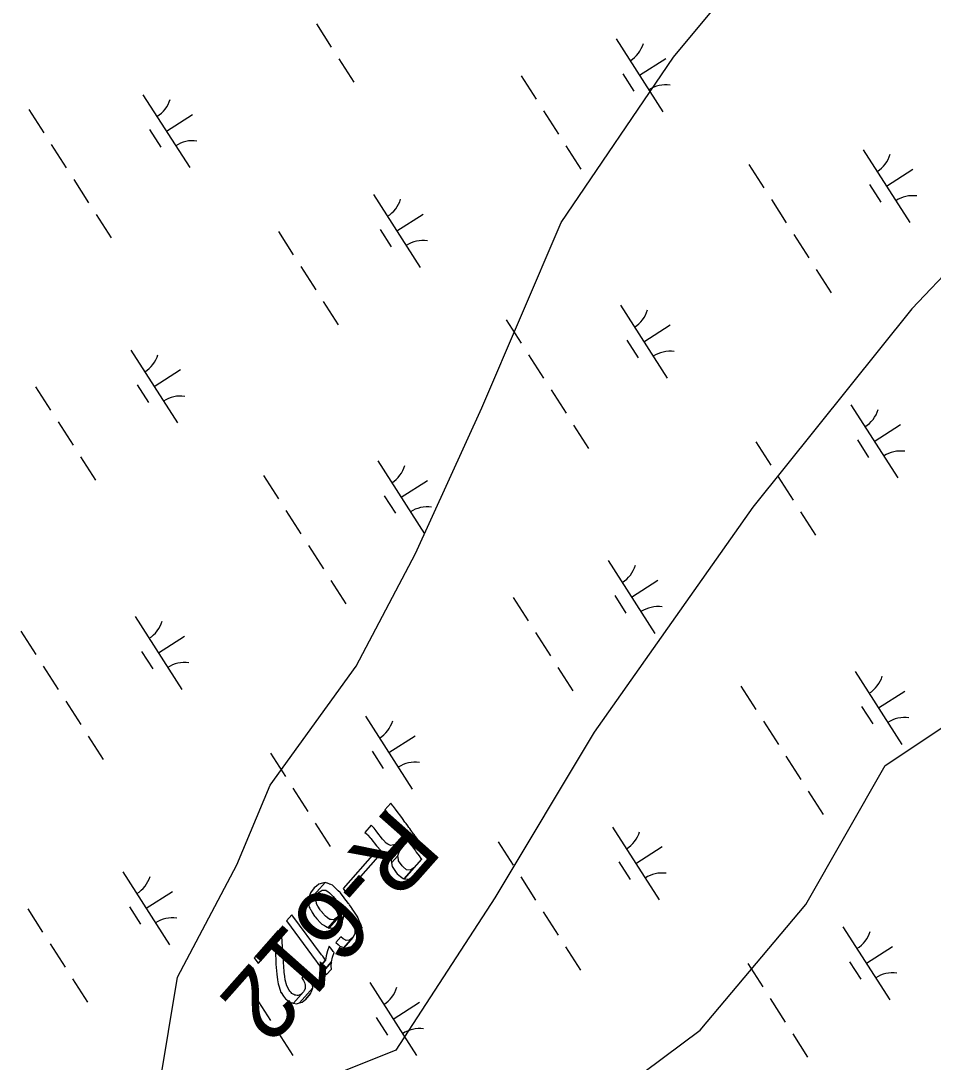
# Model space of a CAD drawing. Extents: x 3962991 to 3983549, y 181631 to 204078.
# Drawn here: x 3978966 to 3979493, y 189800 to 190401 of the extents above; entities that cross this region are included whole.
import ezdxf

# ---------------------------------------------------------------- set-up
doc = ezdxf.new("R2010")
doc.units = 0
for name, color, linetype in [('V-ANNO-MASK', 7, 'Continuous'), ('V-ANNO-MASK2', 7, 'Continuous'), ('V-RIVR-RANG-IDEN', 7, 'Continuous'), ('V-SITE-VEGE', 7, 'Continuous'), ('V-WETL-SWMP', 7, 'Continuous')]:
    doc.layers.add(name, color=color, linetype=linetype)

msp = doc.modelspace()

# ---------------------------------------------------------------- linework, layer by layer
at = {"layer": 'V-ANNO-MASK2'}
for points in [[(3979181.04, 189948.26), (3979179.85, 189949.87), (3979176.44, 189946.02), (3979177.63, 189944.41), (3979177.88, 189944.07), (3979179.1, 189942.43), (3979179.46, 189941.93), (3979182.68, 189937.59), (3979183.08, 189937.04), (3979184.58, 189935.01), (3979185.2, 189934.18), (3979186.18, 189932.84), (3979186.89, 189931.88), (3979187.12, 189931.58), (3979187.31, 189931.32), (3979177.97, 189920.78), (3979179.61, 189920.89), (3979182.21, 189922.34), (3979181.06, 189920.51), (3979179.97, 189917.41), (3979180.03, 189917.04), (3979189.75, 189928.01), (3979189.87, 189927.86), (3979190.5, 189927), (3979191.55, 189925.59), (3979191.89, 189925.13), (3979193.98, 189922.3), (3979194.53, 189921.56), (3979196.09, 189919.45), (3979197.23, 189917.91), (3979197.47, 189917.59), (3979197.47, 189917.59), (3979197.57, 189917.46), (3979197.61, 189917.39), (3979187.58, 189906.06), (3979191.21, 189905.86), (3979194.53, 189907.72), (3979197.6, 189910.93), (3979203.62, 189917.72), (3979203.51, 189917.86), (3979202.76, 189918.89), (3979201.02, 189921.24), (3979200.97, 189921.3), (3979200.87, 189921.43), (3979200.64, 189921.75), (3979199.5, 189923.3), (3979197.94, 189925.4), (3979197.39, 189926.15), (3979195.29, 189928.98), (3979194.96, 189929.43), (3979193.91, 189930.85), (3979193.28, 189931.71), (3979193.16, 189931.86), (3979192.99, 189932.1), (3979192.23, 189933.13), (3979192.02, 189933.42), (3979191.42, 189934.22), (3979190.72, 189935.17), (3979190.53, 189935.43), (3979190.3, 189935.73), (3979189.59, 189936.7), (3979188.61, 189938.02), (3979187.99, 189938.86), (3979186.49, 189940.89), (3979186.09, 189941.44), (3979182.87, 189945.78), (3979182.51, 189946.28), (3979181.29, 189947.91)], [(3979169.9, 189935.68), (3979168.53, 189937.1), (3979164.81, 189932.9), (3979166.32, 189931.63), (3979166.61, 189931.34), (3979167.98, 189929.87), (3979168.36, 189929.39), (3979171.63, 189925.12), (3979172.05, 189924.58), (3979173.76, 189922.79), (3979174.46, 189922.05), (3979175.94, 189921.28), (3979177.01, 189920.72), (3979177.53, 189920.76), (3979177.97, 189920.78), (3979184.09, 189927.69), (3979182.08, 189925.89), (3979181.49, 189925.78), (3979179.6, 189925.41), (3979178.1, 189926.17), (3979177.16, 189926.63), (3979175.51, 189928.49), (3979175.06, 189928.98), (3979171.84, 189933.32), (3979171.46, 189933.8), (3979170.19, 189935.38)], [(3979172.59, 189918.75), (3979170.68, 189921.33), (3979152.24, 189900.51), (3979154.15, 189897.92)], [(3979184.83, 189922.17), (3979186.96, 189924.86), (3979180.03, 189917.04), (3979180.07, 189916.79), (3979180.27, 189915.45), (3979183.8, 189919.43)], [(3979184.21, 189917.3), (3979183.8, 189919.43), (3979180.27, 189915.45), (3979180.61, 189913.23), (3979180.93, 189912.76), (3979182.94, 189909.83), (3979183.46, 189909.06), (3979185.49, 189907.48), (3979186.98, 189906.33), (3979187.28, 189906.08), (3979187.49, 189906.07), (3979193.11, 189912.42), (3979192.56, 189912.04), (3979191.25, 189911.15), (3979188.93, 189911.36), (3979186.99, 189913.04), (3979186.3, 189913.63), (3979184.34, 189916.61)], [(3979194.86, 189914.28), (3979193.1, 189912.41), (3979187.49, 189906.07), (3979187.58, 189906.06)], [(3979136.93, 189902), (3979135.66, 189900.9), (3979133.4, 189898.01), (3979133.2, 189897.44), (3979133.21, 189897.45), (3979132.09, 189894.25), (3979132.24, 189893.19), (3979141.91, 189904.11), (3979140.47, 189903.72), (3979138.21, 189903.1)], [(3979143.14, 189903.66), (3979141.9, 189904.1), (3979132.24, 189893.19), (3979132.46, 189891.6), (3979138.56, 189898.48), (3979139.03, 189898.77), (3979140.31, 189899.55), (3979141.08, 189899.55), (3979141.33, 189899.55), (3979142.31, 189899.54), (3979143.01, 189899.07), (3979143.4, 189898.81), (3979144.53, 189898.03), (3979146.16, 189896.26), (3979146.5, 189895.89), (3979147.51, 189894.79), (3979147.63, 189894.61), (3979149.1, 189892.35), (3979149.77, 189891.31), (3979149.83, 189891.07), (3979149.84, 189891.08), (3979150.37, 189889.13), (3979150.57, 189888.38), (3979150.29, 189886.28), (3979150.26, 189886.03), (3979148.95, 189883.87), (3979143.7, 189877.94), (3979144.08, 189877.73), (3979144.21, 189877.74), (3979152.89, 189887.54), (3979152.91, 189887.51), (3979153.77, 189886.3), (3979154.34, 189885.5), (3979154.49, 189885.28), (3979155.34, 189884.07), (3979157.63, 189880.55), (3979157.68, 189880.45), (3979157.77, 189880.25), (3979158.55, 189878.46), (3979159.1, 189877.22), (3979159.11, 189877.02), (3979159.12, 189876.24), (3979159.16, 189874.54), (3979158.85, 189873.98), (3979157.88, 189872.23), (3979152.72, 189866.42), (3979152.85, 189866.37), (3979152.85, 189866.37), (3979153.57, 189866.1), (3979157.12, 189867.02), (3979162.71, 189873.33), (3979163.09, 189876.85), (3979163.22, 189878.08), (3979163.17, 189878.21), (3979162.99, 189878.65), (3979162.93, 189878.8), (3979162.44, 189879.99), (3979162.22, 189880.53), (3979162.16, 189880.67), (3979161.63, 189881.94), (3979160.88, 189883.76), (3979160.79, 189883.97), (3979160.74, 189884.06), (3979158.41, 189887.53), (3979157.58, 189888.76), (3979157.43, 189888.99), (3979156.88, 189889.81), (3979156.04, 189891.05), (3979156.02, 189891.08), (3979155.96, 189891.15), (3979155.7, 189891.5), (3979155.42, 189891.86), (3979155.34, 189891.98), (3979154.61, 189892.94), (3979154.21, 189893.47), (3979153.16, 189894.83), (3979153.04, 189895), (3979152.3, 189895.97), (3979150.7, 189898.08), (3979150.55, 189898.22), (3979149.49, 189899.26), (3979149.13, 189899.61), (3979147.42, 189901.28), (3979146.44, 189902.24), (3979146.1, 189902.57), (3979145.27, 189902.88), (3979144.52, 189903.15), (3979144.33, 189903.22), (3979143.74, 189903.43), (3979143.3, 189903.59)], [(3979137.21, 189896.72), (3979138.56, 189898.48), (3979132.46, 189891.6), (3979132.49, 189891.38)], [(3979136.9, 189895.71), (3979137.21, 189896.72), (3979132.49, 189891.38), (3979132.57, 189890.81), (3979132.67, 189890.05), (3979132.7, 189889.81), (3979133.1, 189889.14), (3979133.55, 189888.39), (3979133.8, 189887.97), (3979134.54, 189886.74), (3979135.82, 189884.58), (3979136.16, 189884.2), (3979137.16, 189883.09), (3979137.16, 189883.1), (3979137.29, 189882.94), (3979139.05, 189881), (3979139.85, 189880.1), (3979139.98, 189879.95), (3979141.51, 189879.13), (3979142.1, 189878.81), (3979143.17, 189878.23), (3979143.29, 189878.16), (3979143.7, 189877.94), (3979148.95, 189883.87), (3979147.4, 189882.81), (3979146.93, 189882.48), (3979145.46, 189882.61), (3979144.65, 189882.67), (3979143.28, 189883.68), (3979143.13, 189883.8), (3979142.16, 189884.51), (3979140.45, 189886.51), (3979140.32, 189886.67), (3979139.35, 189887.8), (3979139.08, 189888.26), (3979137.78, 189890.4), (3979137.04, 189891.63), (3979136.93, 189892.21), (3979136.72, 189893.22), (3979136.54, 189894.14), (3979136.49, 189894.37)], [(3979139.89, 189862.31), (3979122.79, 189885.44), (3979119.58, 189881.82), (3979136.69, 189858.7), (3979137.33, 189857.83), (3979138.15, 189856.73), (3979139.02, 189855.55), (3979142.22, 189859.16), (3979141.35, 189860.34), (3979140.53, 189861.44)], [(3979152.89, 189887.49), (3979152.89, 189887.54), (3979144.21, 189877.74), (3979144.26, 189877.75), (3979146.36, 189877.93), (3979147.73, 189878.04), (3979148.82, 189878.86), (3979150.46, 189880.11), (3979152.28, 189882.77), (3979152.42, 189883.33), (3979152.93, 189885.35)], [(3979116.92, 189873.39), (3979114.79, 189876.29), (3979100.92, 189860.62), (3979103.06, 189857.73), (3979103.31, 189857.38), (3979113.12, 189868.45), (3979113.32, 189862.42), (3979113.45, 189859.39), (3979113.55, 189856.91), (3979113.83, 189853.06), (3979113.98, 189851.09), (3979114.46, 189847.86), (3979114.81, 189845.47), (3979115.38, 189843.78), (3979116.46, 189840.58), (3979116.47, 189840.54), (3979117.98, 189838.39), (3979118.47, 189837.69), (3979119.04, 189836.86), (3979119.63, 189836.46), (3979119.98, 189836.2), (3979120.66, 189835.73), (3979121.23, 189835.32), (3979121.62, 189835.04), (3979122.06, 189834.73), (3979122.59, 189834.63), (3979123.09, 189834.53), (3979123.49, 189834.45), (3979123.61, 189834.43), (3979123.68, 189834.41), (3979129.53, 189841.02), (3979128.97, 189840.48), (3979128.06, 189839.61), (3979127.29, 189839.27), (3979126.33, 189838.84), (3979125.75, 189838.9), (3979125.09, 189838.96), (3979124.49, 189839.01), (3979123.87, 189839.35), (3979123.14, 189839.76), (3979122.75, 189839.98), (3979122.28, 189840.52), (3979121.63, 189841.26), (3979121.08, 189841.89), (3979119.87, 189844.38), (3979119.85, 189844.41), (3979118.96, 189847.82), (3979118.68, 189849.84), (3979118.33, 189852.24), (3979118.05, 189855.7), (3979117.89, 189857.64), (3979117.63, 189861.51), (3979117.46, 189863.93), (3979117.3, 189866.91), (3979116.96, 189872.78)], [(3979152.36, 189871.47), (3979151.07, 189872.69), (3979148.14, 189869.37), (3979149.44, 189868.17), (3979150.35, 189867.34), (3979150.45, 189867.24), (3979150.98, 189867.05), (3979152.15, 189866.62), (3979152.29, 189866.57), (3979152.72, 189866.42), (3979157.88, 189872.24), (3979156.06, 189870.83), (3979155.86, 189870.81), (3979154.09, 189870.55), (3979153.61, 189870.81), (3979153.48, 189870.88)], [(3979162.46, 189872.95), (3979162.71, 189873.33), (3979157.12, 189867.02), (3979157.23, 189867.05), (3979160.25, 189869.64), (3979160.26, 189869.65)], [(3979144.93, 189866.42), (3979144.29, 189867.28), (3979143.26, 189864.53), (3979142.49, 189861.63), (3979142.22, 189859.16), (3979139.02, 189855.55), (3979139.46, 189854.96), (3979140.14, 189854.04), (3979140.99, 189852.88), (3979145.68, 189858.18), (3979146.25, 189860.94), (3979147.06, 189863.54), (3979146.62, 189864.13), (3979145.75, 189865.31)], [(3979145.45, 189855.69), (3979145.68, 189858.18), (3979140.99, 189852.88), (3979141.89, 189851.67), (3979142.6, 189850.71), (3979145.58, 189854.08)], [(3979132.25, 189851.77), (3979131.68, 189852.61), (3979128.45, 189848.96), (3979129.02, 189848.13), (3979129.43, 189847.53), (3979129.69, 189847.16), (3979130.03, 189846.3), (3979130.31, 189845.58), (3979130.5, 189845.08), (3979130.5, 189844.26), (3979130.5, 189843.56), (3979130.5, 189842.89), (3979129.84, 189841.61), (3979129.65, 189841.25), (3979129.53, 189841.02), (3979123.68, 189834.41), (3979125.31, 189834.09), (3979127.19, 189834.61), (3979134.77, 189843.17), (3979134.72, 189844.72), (3979134.65, 189846.81), (3979134.65, 189846.9), (3979134.61, 189847), (3979134.46, 189847.37), (3979134.29, 189847.83), (3979134.09, 189848.31), (3979133.87, 189848.88), (3979133.67, 189849.38), (3979133.39, 189850.1), (3979132.92, 189850.8), (3979132.66, 189851.18)], [(3979133.98, 189841.04), (3979134.77, 189843.16), (3979127.19, 189834.61), (3979128.64, 189835), (3979130.54, 189836.53), (3979133.58, 189839.96)], [(3979131.41, 189837.22), (3979133.57, 189839.95), (3979130.54, 189836.53), (3979131.41, 189837.22)]]:
    msp.add_lwpolyline(points, close=True, dxfattribs=at)
at = {"layer": 'V-SITE-VEGE'}
for p, q in [((3979342.99, 190380.22), (3979434.6, 190490.98)), ((3979278.1, 190284.74), (3979342.99, 190380.22)), ((3979556.75, 190315.3), (3979480.41, 190235.1)), ((3979232.3, 190177.81), (3979278.1, 190284.74)), ((3979480.41, 190235.1), (3979388.8, 190120.52)), ((3979194.13, 190093.78), (3979232.3, 190177.81)), ((3979388.8, 190120.52), (3979297.19, 189990.67)), ((3979159.77, 190028.86), (3979194.13, 190093.78)), ((3979465.14, 189971.57), (3979591.1, 190055.59)), ((3979110.15, 189960.11), (3979159.77, 190028.86)), ((3979297.19, 189990.67), (3979239.93, 189895.18)), ((3979419.33, 189891.36), (3979465.14, 189971.57)), ((3979091.07, 189914.28), (3979110.15, 189960.11)), ((3979056.71, 189849.36), (3979091.07, 189914.28)), ((3979239.93, 189895.18), (3979182.68, 189807.34)), ((3979358.27, 189818.8), (3979419.33, 189891.36)), ((3979045.26, 189780.61), (3979056.71, 189849.36)), ((3979209.4, 189708.04), (3979358.27, 189818.8)), ((3979182.68, 189807.34), (3979087.25, 189769.15))]:
    msp.add_line(p, q, dxfattribs=at)
at = {"layer": 'V-WETL-SWMP'}
for p, q in [((3979136.87, 190399.46), (3979145.5, 190385.99)), ((3979309.87, 190390.8), (3979336.85, 190348.71)), ((3979149.82, 190379.26), (3979158.46, 190365.79)), ((3979323.36, 190369.76), (3979338.51, 190379.47)), ((3979313.63, 190370.64), (3979320.1, 190360.54)), ((3979254.96, 190369.51), (3979263.6, 190356.04)), ((3979036.81, 190358.57), (3979063.8, 190316.48)), ((3978970.93, 190350.1), (3978979.57, 190336.63)), ((3979050.3, 190337.53), (3979065.46, 190347.24)), ((3979267.91, 190349.3), (3979276.55, 190335.83)), ((3979040.57, 190338.41), (3979047.05, 190328.31)), ((3978983.88, 190329.89), (3978992.52, 190316.42)), ((3979280.87, 190329.1), (3979289.5, 190315.63)), ((3979452.32, 190326.85), (3979479.3, 190284.76)), ((3979386.44, 190318.38), (3979395.07, 190304.91)), ((3979465.81, 190305.81), (3979480.96, 190315.52)), ((3978996.84, 190309.69), (3979005.47, 190296.22)), ((3979456.08, 190306.69), (3979462.55, 190296.59)), ((3979169.84, 190301.03), (3979196.82, 190258.94)), ((3979399.39, 190298.17), (3979408.02, 190284.7)), ((3979009.79, 190289.48), (3979018.42, 190276.01)), ((3979183.33, 190279.98), (3979198.48, 190289.7)), ((3979173.59, 190280.87), (3979180.07, 190270.77)), ((3979114.93, 190279.73), (3979123.57, 190266.26)), ((3979412.34, 190277.97), (3979420.98, 190264.5)), ((3979127.88, 190259.53), (3979136.52, 190246.06)), ((3979425.29, 190257.76), (3979433.93, 190244.3)), ((3979140.84, 190239.32), (3979149.47, 190225.85)), ((3979312.28, 190237.08), (3979339.27, 190194.99)), ((3979246.4, 190228.6), (3979255.04, 190215.13)), ((3979325.78, 190216.03), (3979340.93, 190225.75)), ((3979316.04, 190216.92), (3979322.52, 190206.82)), ((3979029.8, 190211.26), (3979056.79, 190169.16)), ((3979259.36, 190208.4), (3979267.99, 190194.93)), ((3979043.3, 190190.21), (3979058.45, 190199.92)), ((3979033.56, 190191.1), (3979040.04, 190180.99)), ((3978974.9, 190189.96), (3978983.53, 190176.49)), ((3979272.31, 190188.2), (3979280.94, 190174.73)), ((3979445.31, 190179.54), (3979472.29, 190137.44)), ((3978987.85, 190169.76), (3978996.49, 190156.29)), ((3979285.26, 190167.99), (3979293.9, 190154.52)), ((3979458.8, 190158.49), (3979473.95, 190168.21)), ((3979390.4, 190158.24), (3979399.04, 190144.77)), ((3979449.07, 190159.38), (3979455.54, 190149.28)), ((3979000.8, 190149.55), (3979009.44, 190136.08)), ((3979172.25, 190147.31), (3979199.24, 190105.21)), ((3979106.37, 190138.83), (3979115.01, 190125.36)), ((3979185.75, 190126.26), (3979200.9, 190135.97)), ((3979403.36, 190138.04), (3979411.99, 190124.57)), ((3979176.01, 190127.15), (3979182.49, 190117.04)), ((3979119.32, 190118.63), (3979127.96, 190105.16)), ((3979416.31, 190117.83), (3979424.94, 190104.36)), ((3979132.28, 190098.42), (3979140.91, 190084.95)), ((3979305.28, 190089.76), (3979332.26, 190047.67)), ((3979145.23, 190078.22), (3979153.87, 190064.75)), ((3979318.77, 190068.72), (3979333.92, 190078.43)), ((3979250.37, 190068.47), (3979259.01, 190055)), ((3979309.04, 190069.6), (3979315.51, 190059.5)), ((3979032.22, 190057.53), (3979059.21, 190015.44)), ((3978966.34, 190049.06), (3978974.98, 190035.59)), ((3979045.71, 190036.49), (3979060.87, 190046.2)), ((3979263.32, 190048.26), (3979271.96, 190034.79)), ((3979035.98, 190037.37), (3979042.46, 190027.27)), ((3978979.29, 190028.85), (3978987.93, 190015.38)), ((3979276.28, 190028.06), (3979284.91, 190014.59)), ((3979447.73, 190025.81), (3979474.71, 189983.72)), ((3979381.85, 190017.34), (3979390.48, 190003.87)), ((3979461.22, 190004.77), (3979476.37, 190014.48)), ((3978992.25, 190008.65), (3979000.88, 189995.18)), ((3979451.48, 190005.65), (3979457.96, 189995.55)), ((3979165.24, 189999.99), (3979192.23, 189957.9)), ((3979394.8, 189997.13), (3979403.43, 189983.66)), ((3979005.2, 189988.44), (3979013.83, 189974.97)), ((3979178.74, 189978.94), (3979193.89, 189988.66)), ((3979169, 189979.83), (3979175.48, 189969.73)), ((3979110.34, 189978.69), (3979118.98, 189965.22)), ((3979407.75, 189976.93), (3979416.39, 189963.46)), ((3979123.29, 189958.49), (3979131.93, 189945.02)), ((3979420.7, 189956.72), (3979429.34, 189943.26)), ((3979136.25, 189938.28), (3979144.88, 189924.81)), ((3979307.69, 189936.04), (3979334.68, 189893.95)), ((3979241.81, 189927.56), (3979250.45, 189914.1)), ((3979321.19, 189914.99), (3979336.34, 189924.71)), ((3979311.45, 189915.88), (3979317.93, 189905.78)), ((3979025.21, 189910.22), (3979052.2, 189868.12)), ((3979254.77, 189907.36), (3979263.4, 189893.89)), ((3979038.71, 189889.17), (3979053.86, 189898.88)), ((3979028.97, 189890.06), (3979035.45, 189879.95)), ((3978970.31, 189888.92), (3978978.94, 189875.45)), ((3979267.72, 189887.16), (3979276.35, 189873.69)), ((3979440.72, 189878.5), (3979467.7, 189836.4)), ((3978983.26, 189868.72), (3978991.9, 189855.25)), ((3979280.67, 189866.95), (3979289.31, 189853.48)), ((3979454.21, 189857.45), (3979469.36, 189867.17)), ((3979385.81, 189857.2), (3979394.45, 189843.73)), ((3979444.48, 189858.34), (3979450.95, 189848.24)), ((3978996.21, 189848.51), (3979004.85, 189835.04)), ((3979167.66, 189846.27), (3979194.65, 189804.17)), ((3979101.78, 189837.79), (3979110.42, 189824.32)), ((3979398.77, 189837), (3979407.4, 189823.53)), ((3979181.16, 189825.22), (3979196.31, 189834.93)), ((3979171.42, 189826.11), (3979177.9, 189816)), ((3979114.73, 189817.59), (3979123.37, 189804.12)), ((3979411.72, 189816.79), (3979420.35, 189803.32))]:
    msp.add_line(p, q, dxfattribs=at)
for centre, start, end in [((3979308.65, 190393.14), 301.89187, 343.43553), ((3979338.47, 190346.63), 81.89186, 123.43552), ((3979035.6, 190360.91), 301.89187, 343.43553), ((3979065.41, 190314.4), 81.89186, 123.43552), ((3979451.1, 190329.19), 301.89187, 343.43553), ((3979168.62, 190303.36), 301.89187, 343.43553), ((3979480.92, 190282.68), 81.89186, 123.43552), ((3979198.44, 190256.86), 81.89186, 123.43552), ((3979311.07, 190239.41), 301.89187, 343.43553), ((3979028.59, 190213.59), 301.89187, 343.43553), ((3979340.88, 190192.91), 81.89186, 123.43552), ((3979058.4, 190167.08), 81.89186, 123.43552), ((3979444.09, 190181.87), 301.89187, 343.43553), ((3979473.91, 190135.37), 81.89186, 123.43552), ((3979171.04, 190149.64), 301.89187, 343.43553), ((3979200.85, 190103.13), 81.89186, 123.43552), ((3979304.06, 190092.1), 301.89187, 343.43553), ((3979333.88, 190045.59), 81.89186, 123.43552), ((3979031.01, 190059.87), 301.89187, 343.43553), ((3979060.82, 190013.36), 81.89186, 123.43552), ((3979446.51, 190028.15), 301.89187, 343.43553), ((3979476.33, 189981.64), 81.89186, 123.43552), ((3979164.03, 190002.33), 301.89187, 343.43553), ((3979193.84, 189955.82), 81.89186, 123.43552), ((3979306.48, 189938.37), 301.89187, 343.43553), ((3979336.29, 189891.87), 81.89186, 123.43552), ((3979024, 189912.55), 301.89187, 343.43553), ((3979053.81, 189866.05), 81.89186, 123.43552), ((3979439.5, 189880.83), 301.89187, 343.43553), ((3979469.32, 189834.33), 81.89186, 123.43552), ((3979166.45, 189848.6), 301.89187, 343.43553), ((3979196.26, 189802.09), 81.89186, 123.43552)]:
    msp.add_arc(centre, 17.62, start, end, dxfattribs=at)

# ---------------------------------------------------------------- texts
at = {"layer": 'V-ANNO-MASK'}
msp.add_text('R-612  ', height=41.5, rotation=228.47406, dxfattribs=at).set_placement((3979179.43, 189949.4))
at = {"layer": 'V-RIVR-RANG-IDEN'}
msp.add_text('R-612  ', height=41.5, rotation=228.47406, dxfattribs=at).set_placement((3979179.43, 189949.4))

doc.saveas('drawing.dxf')
